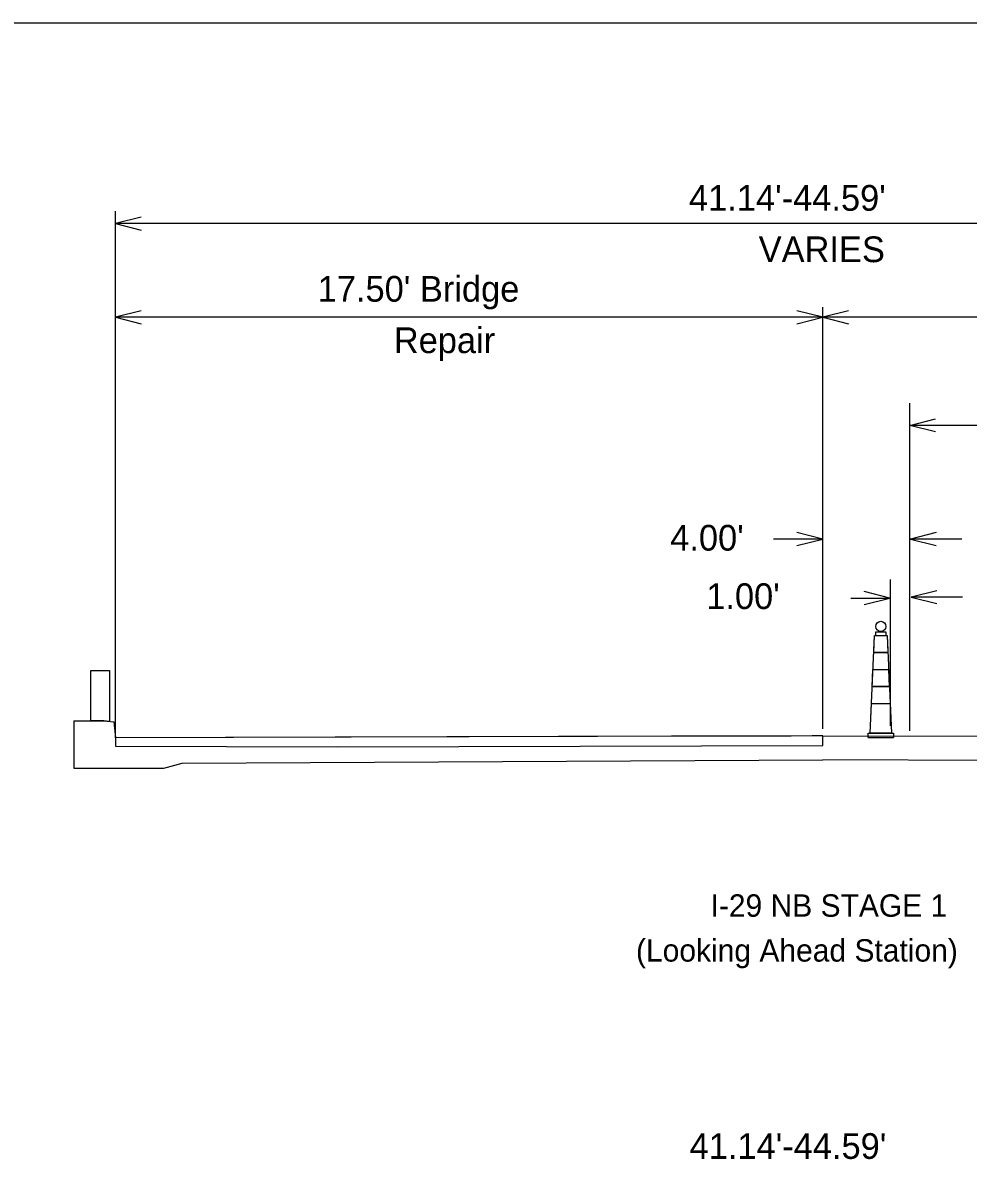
# Model space of a CAD drawing. Extents: x 8771 to 81668, y 6145 to 11018.
# Drawn here: x 10967 to 11801, y 8940 to 9944 of the extents above; entities that cross this region are included whole.
import ezdxf

# ---------------------------------------------------------------- set-up
doc = ezdxf.new("R2010")
doc.units = 0
for name, color, linetype in [('dsnCellElements', 7, 'Continuous'), ('DsnShtRevisedText', 7, 'Continuous'), ('Level 8', 7, 'Continuous'), ('SheetBorder', 7, 'Continuous'), ('ShtPlotIdentification', 7, 'Continuous')]:
    doc.layers.add(name, color=color, linetype=linetype)

msp = doc.modelspace()

# ---------------------------------------------------------------- linework, layer by layer
at = {"layer": 'dsnCellElements'}
for p, q in [((11048.5, 9312.7), (11048.5, 9777.5)), ((12297.1, 9766.6), (11048.5, 9766.6)), ((11672.8, 9320.5), (11672.8, 9692.9)), ((11672.8, 9683.9), (11048.5, 9683.9)), ((12297.1, 9683.9), (11672.8, 9683.9)), ((11749.8, 9318.9), (11749.8, 9608)), ((12023.5, 9588.5), (11749.8, 9588.5)), ((11672.8, 9488.1), (11629.4, 9488.1)), ((11795.7, 9488.1), (11750.3, 9488.1)), ((11732.6, 9323.1), (11732.6, 9452.5)), ((11697.5, 9436), (11732.2, 9436)), ((11796.2, 9436.8), (11750.8, 9436.8)), ((11038.1, 9327.5), (11026.6, 9327.5)), ((11043.3, 9327), (11038.1, 9327.5)), ((11107.3, 9290.3), (11672.8, 9293.3)), ((12238.3, 9290.3), (11672.8, 9293.3)), ((11091.1, 9285.9), (11107.3, 9290.3))]:
    msp.add_line(p, q, dxfattribs=at)
for points in [[(11071.2, 9772.3), (11048.5, 9766.6), (11071.2, 9760.9)], [(11071.2, 9689.6), (11048.5, 9683.9), (11071.2, 9678.2)], [(11650.1, 9678.2), (11672.8, 9683.9), (11650.1, 9689.6)], [(11695.5, 9689.6), (11672.8, 9683.9), (11695.5, 9678.2)], [(11772.5, 9582.8), (11749.8, 9588.5), (11772.5, 9594.2)], [(11650.1, 9482.4), (11672.8, 9488.1), (11650.1, 9493.8)], [(11773, 9493.8), (11750.3, 9488.1), (11773, 9482.4)], [(11709.5, 9430.4), (11732.2, 9436), (11709.5, 9441.7)], [(11773.5, 9442.5), (11750.8, 9436.8), (11773.5, 9431.1)], [(11026.6, 9327.5), (11026.6, 9372), (11043.3, 9372), (11043.3, 9327)], [(11011.6, 9327.5), (11011.6, 9285.9), (11091.1, 9285.9)], [(11011.6, 9327.5), (11038.1, 9327.5), (11047.1, 9326.6), (11048.5, 9312.7)]]:
    msp.add_lwpolyline(points, dxfattribs=at)
at = {"layer": 'DsnShtRevisedText'}
msp.add_lwpolyline([(11026.6, 9327.5), (11026.6, 9372), (11043.3, 9372), (11043.3, 9327)], dxfattribs=at)
at = {"layer": 'Level 8'}
for p, q in [((11714.7, 9316.7), (11718.4, 9402.9)), ((11717.8, 9387.9), (11718.4, 9402.9)), ((11718.4, 9402.9), (11729.7, 9402.9)), ((11718.4, 9402.9), (11729.7, 9402.9)), ((11729.7, 9402.9), (11733.4, 9316.7)), ((11729.7, 9402.9), (11730.3, 9387.9)), ((11717.8, 9387.9), (11730.3, 9387.9)), ((11730.3, 9387.9), (11717.8, 9387.9)), ((11716.5, 9357.9), (11717.1, 9372.9)), ((11717.1, 9372.9), (11731, 9372.9)), ((11717.1, 9372.9), (11731, 9372.9)), ((11731, 9372.9), (11731.6, 9357.9)), ((11716.5, 9357.9), (11731.6, 9357.9)), ((11731.6, 9357.9), (11716.5, 9357.9)), ((11714.7, 9316.7), (11715.8, 9342.9)), ((11715.8, 9342.9), (11732.3, 9342.9)), ((11715.8, 9342.9), (11732.3, 9342.9)), ((11732.3, 9342.9), (11733.4, 9316.7)), ((11712.8, 9316.7), (11735.3, 9316.7)), ((11712.8, 9312.9), (11712.8, 9316.7)), ((11733.4, 9316.7), (11714.7, 9316.7)), ((11735.3, 9316.7), (11735.3, 9312.9)), ((11712.8, 9312.9), (11735.3, 9312.9))]:
    msp.add_line(p, q, dxfattribs=at)
msp.add_lwpolyline([(11728.9, 9405.9), (11719.3, 9405.9), (11719.3, 9402.9), (11728.9, 9402.9)], close=True, dxfattribs=at)
msp.add_circle((11724.1, 9411), 4.5, dxfattribs=at)
at = {"layer": 'SheetBorder'}
msp.add_lwpolyline([(10132.5, 9944), (13267.5, 9944), (13267.5, 7924), (10132.5, 7924)], close=True, dxfattribs=at)
at = {"layer": 'ShtPlotIdentification'}
for p, q in [((11672.8, 9314.4), (11048.5, 9312.7)), ((11672.8, 9314.4), (12297.1, 9312.7)), ((11244.5, 9304.6), (11672.8, 9305.9)), ((11672.8, 9305.9), (11672.8, 9310.6))]:
    msp.add_line(p, q, dxfattribs=at)
for points in [[(11242.3, 9313.3), (11048.5, 9312.7), (11048.5, 9305.1), (11244.5, 9304.6)], [(11672.8, 9310.6), (11672.8, 9314.4), (11663.6, 9314.3), (11645.1, 9314.2), (11619.1, 9314.2), (11586.4, 9314.1), (11539.2, 9314), (11474, 9313.8), (11439.5, 9313.7), (11242.3, 9313.3)]]:
    msp.add_lwpolyline(points, dxfattribs=at)

# ---------------------------------------------------------------- texts
at = {"layer": 'dsnCellElements'}
for s, height, p in [("41.14'-44.59'", 22.709, (11554.8, 9778)), ('VARIES', 22.71, (11616.3, 9732.6)), ("17.50' Bridge", 22.709, (11227, 9697.7)), ('Repair', 22.71, (11294.2, 9652.3)), ("4.00'", 22.71, (11538.2, 9477.9)), ("1.00'", 22.71, (11570, 9426.3)), ('I-29 NB STAGE 1', 19.8, (11573.8, 9154.6)), ('(Looking Ahead Station)', 19.8, (11508, 9115)), ("41.14'-44.59'", 22.709, (11555.3, 8940.8))]:
    msp.add_text(s, height=height, dxfattribs=at).set_placement(p)

doc.saveas('drawing.dxf')
